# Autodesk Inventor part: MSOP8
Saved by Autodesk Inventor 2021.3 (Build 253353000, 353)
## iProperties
Created: 2021-12
Part Number: MSOP8
Material: Generic
Document SubType Name: Modeling
Designer: Administrator
Density: 1 g/cm^3
Appearance: Default
Title: MSOP8
Author: Administrator
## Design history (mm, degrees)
feature "Body1"
body "Solid1"
